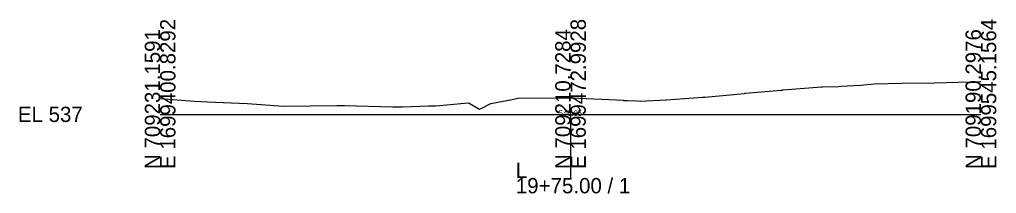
# Model space of a CAD drawing. Extents: x -63 to 1153, y -24 to 9522.
# Drawn here: x 974.3 to 1152.8, y 2985.5 to 3017.4 of the extents above; entities that cross this region are included whole.
import ezdxf

# ---------------------------------------------------------------- set-up
doc = ezdxf.new("R2010")
doc.units = 0
for name, color, linetype in [('Default', 7, 'Continuous'), ('Exist Cross Section Cell', 7, 'Continuous'), ('Exist XS Center Line Elevation Label', 7, 'Continuous'), ('Exist XS Ground Line', 7, 'Continuous')]:
    doc.layers.add(name, color=color, linetype=linetype)

msp = doc.modelspace()

# ---------------------------------------------------------------- linework, layer by layer
at = {"layer": 'Exist Cross Section Cell'}
for p, q in [((1000, 3000), (1075, 3000)), ((1075, 3000), (1150, 3000)), ((1075, 3000), (1075, 2988.34))]:
    msp.add_line(p, q, dxfattribs=at)
at = {"layer": 'Exist XS Ground Line'}
msp.add_lwpolyline([(1000, 3002.91), (1006.22, 3002.41), (1008.67, 3002.27), (1015.97, 3001.96), (1022.51, 3001.51), (1027.42, 3001.54), (1032.38, 3001.63), (1033.72, 3001.62), (1042.53, 3001.38), (1044.31, 3001.35), (1049.09, 3001.58), (1050.37, 3001.59), (1055.6, 3002.08), (1056.4, 3002.11), (1056.47, 3002.07), (1058.36, 3000.97), (1058.66, 3001.1), (1060.43, 3002.01), (1064.36, 3002.72), (1065.39, 3002.94), (1073.75, 3003.03), (1075, 3003.05), (1075.12, 3003.05), (1083.43, 3002.65), (1084.61, 3002.59), (1084.66, 3002.53), (1085.41, 3002.54), (1087.12, 3002.45), (1087.72, 3002.43), (1092.42, 3002.65), (1092.51, 3002.65), (1099.11, 3003.12), (1099.13, 3003.12), (1099.52, 3003.16), (1106.82, 3003.85), (1106.84, 3003.86), (1106.87, 3003.86), (1106.91, 3003.87), (1106.95, 3003.87), (1107, 3003.88), (1113.5, 3004.45), (1113.55, 3004.45), (1113.6, 3004.46), (1113.66, 3004.46), (1113.71, 3004.47), (1113.78, 3004.47), (1113.83, 3004.47), (1120.87, 3005.05), (1120.95, 3005.04), (1121.03, 3005.04), (1121.07, 3005.04), (1123.97, 3005.13), (1123.99, 3005.13), (1124.43, 3005.14), (1128.01, 3005.36), (1130.47, 3005.61), (1135.53, 3005.73), (1141.58, 3005.76), (1150, 3006)], dxfattribs=at)

# ---------------------------------------------------------------- texts
at = {"layer": 'Default'}
msp.add_text('-', height=0.0001, dxfattribs=at).set_placement((1000, 3000))
at = {"layer": 'Exist Cross Section Cell'}
for s, p in [('E 1699400.8292', (1002.8, 2990)), ('E 1699472.9928', (1077.8, 2990)), ('E 1699545.1564', (1152.8, 2990)), ('N 709231.1591', (1000, 2990)), ('N 709210.7284', (1075, 2990)), ('N 709190.2976', (1150, 2990))]:
    msp.add_text(s, height=2.8, rotation=90, dxfattribs=at).set_placement(p)
for s, p in [('EL 537', (974, 2998.6)), ('L', (1065, 2988.34)), ('19+75.00 / 1', (1065, 2985.54))]:
    msp.add_text(s, height=2.8, dxfattribs=at).set_placement(p)
at = {"layer": 'Exist XS Center Line Elevation Label'}
msp.add_text('540.05', height=1, dxfattribs=at).set_placement((1072.87, 2999.72))

doc.saveas('drawing.dxf')
